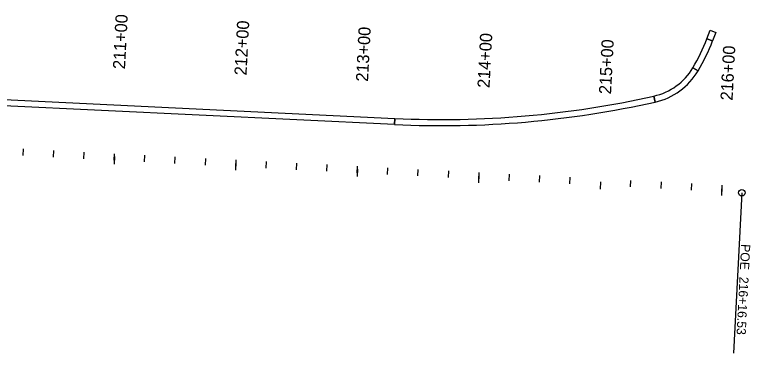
# Model space of a CAD drawing. Extents: x 20499216 to 20505321, y 7953487 to 7960535.
# Drawn here: x 20504716 to 20505321, y 7953487 to 7953765 of the extents above; entities that cross this region are included whole.
import ezdxf

# ---------------------------------------------------------------- set-up
doc = ezdxf.new("R2010")
doc.units = 0
for name, color, linetype in [('EXT_CU', 7, 'Continuous'), ('EXT_RR', 7, 'Continuous'), ('Natural', 7, 'Continuous'), ('Safety', 7, 'Continuous')]:
    doc.layers.add(name, color=color, linetype=linetype)

msp = doc.modelspace()

# ---------------------------------------------------------------- linework, layer by layer
at = {"layer": 'EXT_CU'}
for p, q in [((20505285.29, 7953745.35), (20505289.97, 7953743.59)), ((20505273.8, 7953721.49), (20505278.1, 7953718.93)), ((20505278.1, 7953718.93), (20505273.8, 7953721.49)), ((20505241.76, 7953698.28), (20505242.85, 7953693.4)), ((20505242.85, 7953693.4), (20505241.76, 7953698.28)), ((20505028.64, 7953674.94), (20505028.88, 7953679.93))]:
    msp.add_line(p, q, dxfattribs=at)
for points in [[(20505285.29, 7953745.35), (20505287.94, 7953752.38), (20505292.54, 7953750.41), (20505289.97, 7953743.59)], [(20505028.88, 7953679.93), (20505028.64, 7953674.94), (20504707.53, 7953690.4), (20504707.7, 7953695.4)]]:
    msp.add_lwpolyline(points, close=True, dxfattribs=at)
for centre, radius, start, end in [((20505144.92, 7953798.23), 150, 329.2295, 339.35686), ((20505144.92, 7953798.23), 155, 329.2295, 339.35686), ((20505230.84, 7953747.07), 50, 282.60964, 329.2295), ((20505230.84, 7953747.07), 55, 282.60964, 329.2295), ((20505067.33, 7954478), 799, 267.24196, 282.60964), ((20505067.33, 7954478), 804, 267.24196, 282.60964)]:
    msp.add_arc(centre, radius, start, end, dxfattribs=at)
at = {"layer": 'EXT_RR'}
for p, q in [((20504723.31, 7953649.39), (20504723.59, 7953654.85)), ((20504748.28, 7953648.11), (20504748.56, 7953653.56)), ((20504773.25, 7953646.82), (20504773.53, 7953652.27)), ((20504798.37, 7953648.59), (20504798.06, 7953642.48)), ((20504823.18, 7953644.25), (20504823.46, 7953649.7)), ((20504848.15, 7953642.96), (20504848.43, 7953648.41)), ((20504873.11, 7953641.67), (20504873.4, 7953647.12)), ((20504898.24, 7953643.44), (20504897.92, 7953637.33)), ((20504923.05, 7953639.1), (20504923.33, 7953644.55)), ((20504948.01, 7953637.81), (20504948.3, 7953643.26)), ((20504972.98, 7953636.52), (20504973.26, 7953641.98)), ((20505022.91, 7953633.95), (20505023.2, 7953639.4)), ((20504998.11, 7953638.29), (20504997.79, 7953632.18)), ((20505047.88, 7953632.66), (20505048.16, 7953638.11)), ((20505072.85, 7953631.37), (20505073.13, 7953636.83)), ((20505097.97, 7953633.14), (20505097.66, 7953627.03)), ((20505122.78, 7953628.8), (20505123.06, 7953634.25)), ((20505147.75, 7953627.51), (20505148.03, 7953632.97)), ((20505172.72, 7953626.23), (20505173, 7953631.68)), ((20505197.84, 7953627.99), (20505197.53, 7953621.88)), ((20505222.65, 7953623.65), (20505222.93, 7953629.1)), ((20505247.62, 7953622.36), (20505247.9, 7953627.82)), ((20505272.58, 7953621.08), (20505272.86, 7953626.53)), ((20505297.71, 7953622.85), (20505297.39, 7953616.73))]:
    msp.add_line(p, q, dxfattribs=at)
at = {"layer": 'Natural'}
for p in [(20505314.06, 7953618.94), (20505307.27, 7953487.11)]:
    msp.add_line(p, (20505307.27, 7953487.11), dxfattribs=at)
msp.add_circle((20505314.06, 7953618.94), 2.67, dxfattribs=at)
at = {"layer": 'Safety'}
for p, q in [((20504798.21, 7953645.53), (20504798.49, 7953650.99)), ((20504898.08, 7953640.38), (20504898.36, 7953645.84)), ((20504997.95, 7953635.24), (20504998.23, 7953640.69)), ((20505097.82, 7953630.09), (20505098.1, 7953635.54)), ((20505197.84, 7953627.99), (20505197.53, 7953621.88)), ((20505297.55, 7953619.79), (20505297.83, 7953625.24))]:
    msp.add_line(p, q, dxfattribs=at)

# ---------------------------------------------------------------- texts
at = {"layer": 'EXT_RR'}
for s, p in [('211+00', (20504807.08, 7953720.18)), ('212+00', (20504906.95, 7953715.03)), ('213+00', (20505006.81, 7953709.88)), ('214+00', (20505106.68, 7953704.73)), ('215+00', (20505206.55, 7953699.58)), ('216+00', (20505306.42, 7953694.43))]:
    msp.add_text(s, height=10.02, rotation=87.04866, dxfattribs=at).set_placement(p)
at = {"layer": 'Natural'}
for s, p in [('POE ', (20505313.54, 7953576.91)), ('216+16.53', (20505312.16, 7953550.05))]:
    msp.add_text(s, height=7.5, rotation=267.04866, dxfattribs=at).set_placement(p)
at = {"layer": 'Safety'}
msp.add_text('215+00', height=10.02, rotation=87.04866, dxfattribs=at).set_placement((20505206.55, 7953699.58))

doc.saveas('drawing.dxf')
